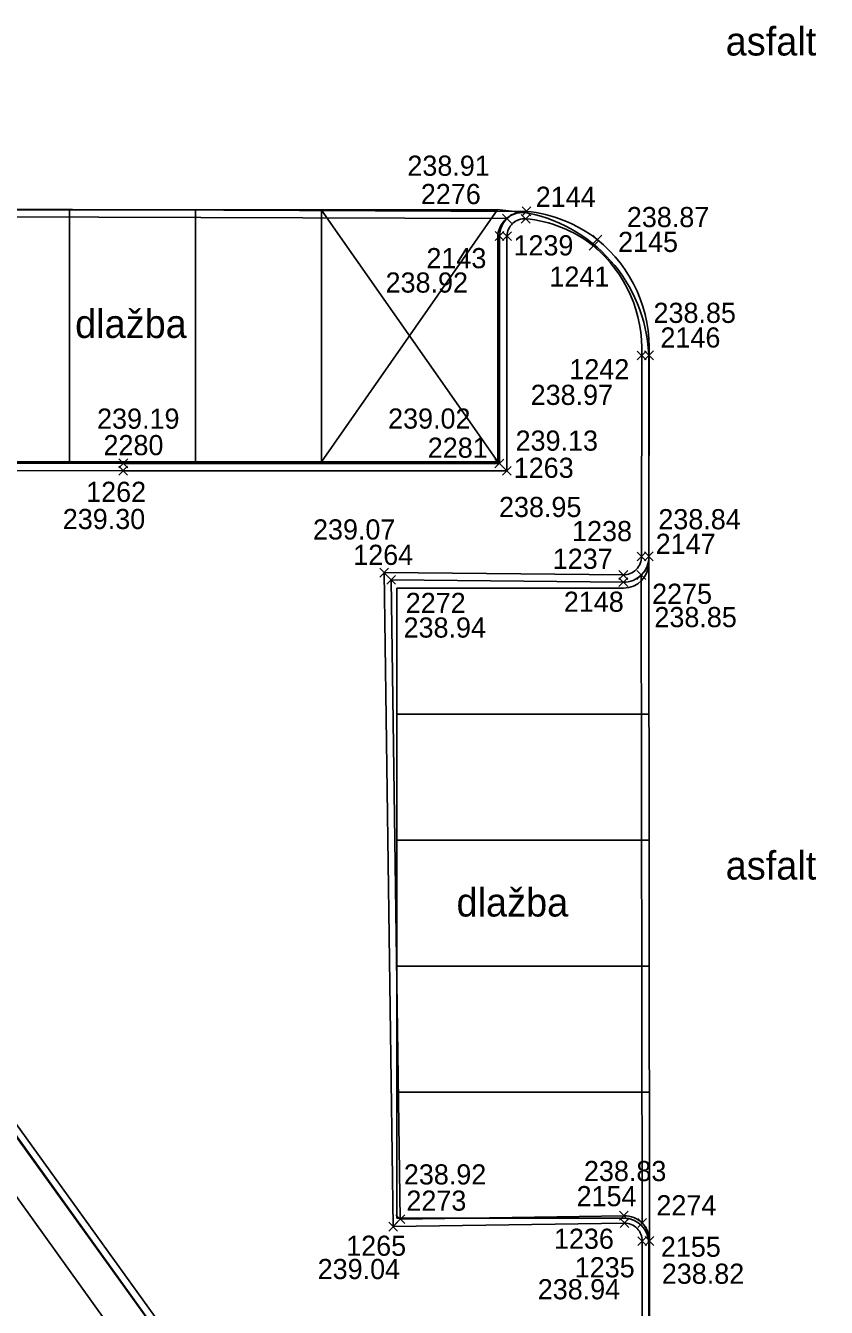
# Model space of a CAD drawing. Extents: x -264222 to -263676, y -1242344 to -1242060.
# Drawn here: x -264143.94 to -264128.04, y -1242272.25 to -1242246.83 of the extents above; entities that cross this region are included whole.
import ezdxf

# ---------------------------------------------------------------- set-up
doc = ezdxf.new("R2010")
doc.units = 0
for name, color, linetype in [('BODY_CISLO', 7, 'Continuous'), ('BODY_SYMBOL', 7, 'Continuous'), ('BODY_VYSKA', 7, 'Continuous'), ('KOORDINACNA_SITUACIA_DSP', 7, 'Continuous'), ('POPIS', 7, 'Continuous'), ('PROJEKT_DRS_OBRUBNIKY_KOMUNIKACIE', 7, 'Continuous'), ('PROJEKT_DRS_TDZ_VODOROVNE', 7, 'Continuous'), ('SO_20-3_OBRUBNIKY_DOLNA_HRANA', 7, 'Continuous'), ('SO_20-3_OBRUBNIKY_HORNA_HRANA', 7, 'Continuous')]:
    doc.layers.add(name, color=color, linetype=linetype)

msp = doc.modelspace()

# ---------------------------------------------------------------- linework, layer by layer
at = {"layer": 'BODY_SYMBOL'}
for p, q in [((-264134.472, -1242250.742), (-264134.296, -1242250.566)), ((-264134.296, -1242250.742), (-264134.472, -1242250.566)), ((-264134.102, -1242250.745), (-264133.926, -1242250.569)), ((-264133.926, -1242250.745), (-264134.102, -1242250.569)), ((-264134.085, -1242250.598), (-264133.909, -1242250.422)), ((-264133.909, -1242250.598), (-264134.085, -1242250.422)), ((-264134.62, -1242251.087), (-264134.444, -1242250.911)), ((-264134.444, -1242251.087), (-264134.62, -1242250.911)), ((-264134.472, -1242251.089), (-264134.296, -1242250.913)), ((-264134.296, -1242251.089), (-264134.472, -1242250.913)), ((-264132.68, -1242251.156), (-264132.504, -1242250.98)), ((-264132.504, -1242251.156), (-264132.68, -1242250.98)), ((-264132.753, -1242251.282), (-264132.577, -1242251.106)), ((-264132.577, -1242251.282), (-264132.753, -1242251.106)), ((-264131.797, -1242253.457), (-264131.621, -1242253.281)), ((-264131.621, -1242253.457), (-264131.797, -1242253.281)), ((-264131.651, -1242253.456), (-264131.475, -1242253.28)), ((-264131.475, -1242253.456), (-264131.651, -1242253.28)), ((-264142.092, -1242255.744), (-264141.916, -1242255.568)), ((-264141.916, -1242255.744), (-264142.092, -1242255.568)), ((-264142.089, -1242255.597), (-264141.913, -1242255.421)), ((-264141.913, -1242255.597), (-264142.089, -1242255.421)), ((-264134.623, -1242255.601), (-264134.447, -1242255.425)), ((-264134.447, -1242255.601), (-264134.623, -1242255.425)), ((-264134.474, -1242255.745), (-264134.298, -1242255.569)), ((-264134.298, -1242255.745), (-264134.474, -1242255.569)), ((-264131.801, -1242257.444), (-264131.625, -1242257.268)), ((-264131.625, -1242257.444), (-264131.801, -1242257.268)), ((-264131.656, -1242257.441), (-264131.48, -1242257.265)), ((-264131.48, -1242257.441), (-264131.656, -1242257.265)), ((-264136.91, -1242257.764), (-264136.734, -1242257.588)), ((-264136.734, -1242257.764), (-264136.91, -1242257.588)), ((-264132.163, -1242257.81), (-264131.987, -1242257.634)), ((-264131.987, -1242257.81), (-264132.163, -1242257.634)), ((-264131.806, -1242257.813), (-264131.63, -1242257.637)), ((-264131.63, -1242257.813), (-264131.806, -1242257.637)), ((-264136.77, -1242257.909), (-264136.594, -1242257.733)), ((-264136.594, -1242257.909), (-264136.77, -1242257.733)), ((-264132.163, -1242257.955), (-264131.987, -1242257.779)), ((-264131.987, -1242257.955), (-264132.163, -1242257.779)), ((-264136.59, -1242270.59), (-264136.414, -1242270.414)), ((-264136.414, -1242270.59), (-264136.59, -1242270.414)), ((-264132.151, -1242270.523), (-264131.975, -1242270.347)), ((-264131.975, -1242270.523), (-264132.151, -1242270.347)), ((-264136.73, -1242270.739), (-264136.554, -1242270.563)), ((-264136.554, -1242270.739), (-264136.73, -1242270.563)), ((-264132.14, -1242270.669), (-264131.964, -1242270.493)), ((-264131.964, -1242270.669), (-264132.14, -1242270.493)), ((-264131.789, -1242270.668), (-264131.613, -1242270.492)), ((-264131.613, -1242270.668), (-264131.789, -1242270.492)), ((-264131.788, -1242271.028), (-264131.612, -1242270.852)), ((-264131.612, -1242271.028), (-264131.788, -1242270.852)), ((-264131.643, -1242271.023), (-264131.467, -1242270.847)), ((-264131.467, -1242271.023), (-264131.643, -1242270.847))]:
    msp.add_line(p, q, dxfattribs=at)
at = {"layer": 'KOORDINACNA_SITUACIA_DSP'}
for p, q in [((-264134.568, -1242255.482), (-264134.568, -1242251.033)), ((-264131.568, -1242257.482), (-264131.568, -1242253.482)), ((-264153.916, -1242255.234), (-264139.439, -1242275.363)), ((-264150.568, -1242255.482), (-264134.568, -1242255.482)), ((-264152.757, -1242258.05), (-264124.146, -1242297.83)), ((-264152.757, -1242258.05), (-264124.146, -1242297.83)), ((-264136.568, -1242257.982), (-264136.568, -1242270.482)), ((-264136.568, -1242257.982), (-264132.068, -1242257.982)), ((-264136.568, -1242270.482), (-264132.068, -1242270.482)), ((-264131.568, -1242270.982), (-264131.568, -1242277.056))]:
    msp.add_line(p, q, dxfattribs=at)
for centre, radius, start, end in [((-264134.068, -1242251.033), 0.5, 78.463, 180), ((-264134.568, -1242253.482), 3, 0, 78.463), ((-264132.068, -1242257.482), 0.5, 270, 0), ((-264132.068, -1242270.982), 0.5, 0, 90)]:
    msp.add_arc(centre, radius, start, end, dxfattribs=at)
at = {"layer": 'PROJEKT_DRS_OBRUBNIKY_KOMUNIKACIE'}
for p, q in [((-264134.568, -1242250.482), (-264150.568, -1242250.482)), ((-264134.581, -1242250.476), (-264134.068, -1242250.533)), ((-264134.568, -1242255.482), (-264134.568, -1242251.033)), ((-264131.568, -1242257.482), (-264131.568, -1242253.482)), ((-264153.916, -1242255.234), (-264139.439, -1242275.363)), ((-264150.568, -1242255.482), (-264134.568, -1242255.482)), ((-264136.568, -1242257.982), (-264136.568, -1242270.482)), ((-264136.568, -1242257.982), (-264132.068, -1242257.982)), ((-264136.568, -1242270.482), (-264132.068, -1242270.482)), ((-264131.568, -1242270.982), (-264131.568, -1242277.056))]:
    msp.add_line(p, q, dxfattribs=at)
for centre, radius, start, end in [((-264134.068, -1242251.033), 0.5, 78.463, 180), ((-264134.568, -1242253.482), 3, 0, 78.463), ((-264132.068, -1242257.482), 0.5, 270, 0), ((-264132.068, -1242270.982), 0.5, 0, 90)]:
    msp.add_arc(centre, radius, start, end, dxfattribs=at)
at = {"layer": 'PROJEKT_DRS_TDZ_VODOROVNE'}
for p, q in [((-264143.068, -1242255.482), (-264143.068, -1242250.482)), ((-264140.568, -1242255.482), (-264140.568, -1242250.482)), ((-264138.068, -1242255.482), (-264138.068, -1242250.482)), ((-264134.581, -1242250.484), (-264138.068, -1242255.482)), ((-264138.066, -1242250.484), (-264134.568, -1242255.482)), ((-264136.568, -1242260.482), (-264131.568, -1242260.482)), ((-264136.568, -1242262.982), (-264131.568, -1242262.982)), ((-264136.568, -1242265.482), (-264131.568, -1242265.482)), ((-264136.568, -1242267.982), (-264131.568, -1242267.982))]:
    msp.add_line(p, q, dxfattribs=at)
at = {"layer": 'SO_20-3_OBRUBNIKY_DOLNA_HRANA'}
for p, q in [((-264151.031, -1242250.44), (-264133.997, -1242250.51)), ((-264134.384, -1242250.654), (-264150.7, -1242250.592)), ((-264131.568, -1242257.353), (-264131.563, -1242253.368)), ((-264131.555, -1242270.935), (-264131.568, -1242257.353)), ((-264131.701, -1242270.58), (-264131.718, -1242257.725)), ((-264131.548, -1242275.925), (-264131.555, -1242270.935))]:
    msp.add_line(p, q, dxfattribs=at)
for points in [[(-264150.565, -1242250.962), (-264150.603, -1242255.49), (-264142.001, -1242255.509), (-264134.535, -1242255.513), (-264134.532, -1242250.999)], [(-264154.16, -1242254.916), (-264146.578, -1242265.475), (-264138.972, -1242276.017)], [(-264132.075, -1242257.867), (-264136.682, -1242257.821), (-264136.502, -1242270.502), (-264132.063, -1242270.435)]]:
    msp.add_lwpolyline(points, dxfattribs=at)
for centre, major_axis, ratio, start_param, end_param in [((-264134.031, -1242251.011), (0.088, -0.494), 0.999099, 2.898819, 4.51404), ((-264134.272, -1242253.247), (-2.666, -0.684), 0.999354, 3.804651, 4.361234), ((-264134.328, -1242253.225), (2.694, 0.641), 0.999979, 5.998124, 6.942783), ((-264132.067, -1242257.368), (0.351, 0.355), 0.999602, 3.903953, 5.520825), ((-264132.051, -1242270.931), (-0.496, -0.002), 0.999873, 3.129279, 4.731059)]:
    msp.add_ellipse(centre, major_axis=major_axis, ratio=ratio, start_param=start_param, end_param=end_param, dxfattribs=at)
at = {"layer": 'SO_20-3_OBRUBNIKY_HORNA_HRANA'}
for p, q in [((-264131.709, -1242253.369), (-264131.713, -1242257.356)), ((-264131.7, -1242270.94), (-264131.693, -1242275.925))]:
    msp.add_line(p, q, dxfattribs=at)
for points in [[(-264150.712, -1242250.956), (-264150.75, -1242255.637), (-264142.004, -1242255.656), (-264134.386, -1242255.657), (-264134.384, -1242251.001)], [(-264138.851, -1242275.933), (-264146.457, -1242265.393), (-264154.039, -1242254.835)], [(-264132.075, -1242257.722), (-264136.822, -1242257.676), (-264136.642, -1242270.651), (-264132.052, -1242270.581)]]:
    msp.add_lwpolyline(points, dxfattribs=at)
for centre, major_axis, ratio, start_param, end_param in [((-264134.033, -1242251.008), (0.028, -0.35), 0.998731, 3.005691, 4.612609), ((-264134.256, -1242253.224), (-2.407, -0.927), 0.999506, 3.680289, 4.250966), ((-264134.38, -1242253.246), (0.97, 2.492), 0.999929, 5.037359, 5.95793), ((-264132.073, -1242257.362), (0.342, 0.112), 0.999272, 4.390828, 5.985608), ((-264132.048, -1242270.929), (0.258, -0.233), 0.999459, 0.702378, 2.318149)]:
    msp.add_ellipse(centre, major_axis=major_axis, ratio=ratio, start_param=start_param, end_param=end_param, dxfattribs=at)

# ---------------------------------------------------------------- texts
at = {"layer": 'BODY_CISLO'}
for s, p in [('2276', (-264136.094, -1242250.366)), ('2144', (-264133.813, -1242250.421)), ('1239', (-264134.255, -1242251.384)), ('2145', (-264132.178, -1242251.316)), ('2143', (-264135.983, -1242251.638)), ('1241', (-264133.541, -1242252.004)), ('2146', (-264131.337, -1242253.212)), ('1242', (-264133.146, -1242253.842)), ('2280', (-264142.394, -1242255.347)), ('2281', (-264135.956, -1242255.398)), ('1263', (-264134.25, -1242255.797)), ('1262', (-264142.738, -1242256.274)), ('1238', (-264133.092, -1242257.052)), ('2147', (-264131.432, -1242257.305)), ('1264', (-264137.436, -1242257.524)), ('1237', (-264133.475, -1242257.602)), ('2275', (-264131.503, -1242258.296)), ('2272', (-264136.394, -1242258.478)), ('2148', (-264133.255, -1242258.454)), ('2154', (-264133.002, -1242270.246)), ('2273', (-264136.381, -1242270.335)), ('2274', (-264131.418, -1242270.428)), ('1265', (-264137.576, -1242271.23)), ('1236', (-264133.452, -1242271.091)), ('2155', (-264131.329, -1242271.25)), ('1235', (-264133.038, -1242271.658))]:
    msp.add_text(s, height=0.4, dxfattribs=at).set_placement(p)
at = {"layer": 'BODY_VYSKA'}
for s, p in [('238.91', (-264136.361, -1242249.804)), ('238.87', (-264132.004, -1242250.823)), ('238.92', (-264136.794, -1242252.122)), ('238.85', (-264131.475, -1242252.723)), ('238.97', (-264133.914, -1242254.35)), ('239.19', (-264142.521, -1242254.822)), ('239.02', (-264136.744, -1242254.82)), ('239.13', (-264134.213, -1242255.258)), ('238.95', (-264134.542, -1242256.574)), ('239.30', (-264143.202, -1242256.813)), ('238.84', (-264131.379, -1242256.817)), ('239.07', (-264138.235, -1242257.02)), ('238.85', (-264131.457, -1242258.759)), ('238.94', (-264136.437, -1242258.966)), ('238.83', (-264132.856, -1242269.748)), ('238.92', (-264136.431, -1242269.815)), ('239.04', (-264138.142, -1242271.692)), ('238.82', (-264131.31, -1242271.785)), ('238.94', (-264133.773, -1242272.093))]:
    msp.add_text(s, height=0.4, dxfattribs=at).set_placement(p)
at = {"layer": 'POPIS'}
for p in [(-264130.042, -1242247.418), (-264130.042, -1242263.767)]:
    msp.add_text('asfalt', height=0.5625, dxfattribs=at).set_placement(p)
for p in [(-264142.957, -1242253.022), (-264135.385, -1242264.499)]:
    msp.add_text('dlažba', height=0.5625, rotation=360, dxfattribs=at).set_placement(p)

doc.saveas('drawing.dxf')
